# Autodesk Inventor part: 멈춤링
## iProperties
IsCustomPart: 0
Created: 2009-02
Part Number: 멈춤링
Material: 강, 연강
Description: 리테이닝 링(C형)
Document SubType Name: Modeling
Standard: KS B 1336
Designer: KYOUNG IL JANG
Standards Organization: KS
Language: ko-KR
Size Designation: 22 x 1.2
Categories: <MemberInstance><Categories><Category DisplayName="샤프트 부품" InternalName="7f7aeb1f-a693-4053-b835-cee3144e0d98" Mnemonic="SHFT"><Category DisplayName="써클립" Inter
Density: 7.86 g/cm^3
Mass: 1.82859 g
Surface Area: 5.91219 cm^2
Volume: 0.232645 cm^3
Author: KYOUNG IL JANG
